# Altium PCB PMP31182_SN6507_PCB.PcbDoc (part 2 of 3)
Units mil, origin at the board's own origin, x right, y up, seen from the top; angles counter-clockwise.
Board outline 4922 x 2266 mil, 4 copper layers (Top Layer, Signal Layer 1, Signal Layer 2, Bottom Layer), stack 77.9 mil thick; 174 components, 102 nets, 540 pads, 580 vias.
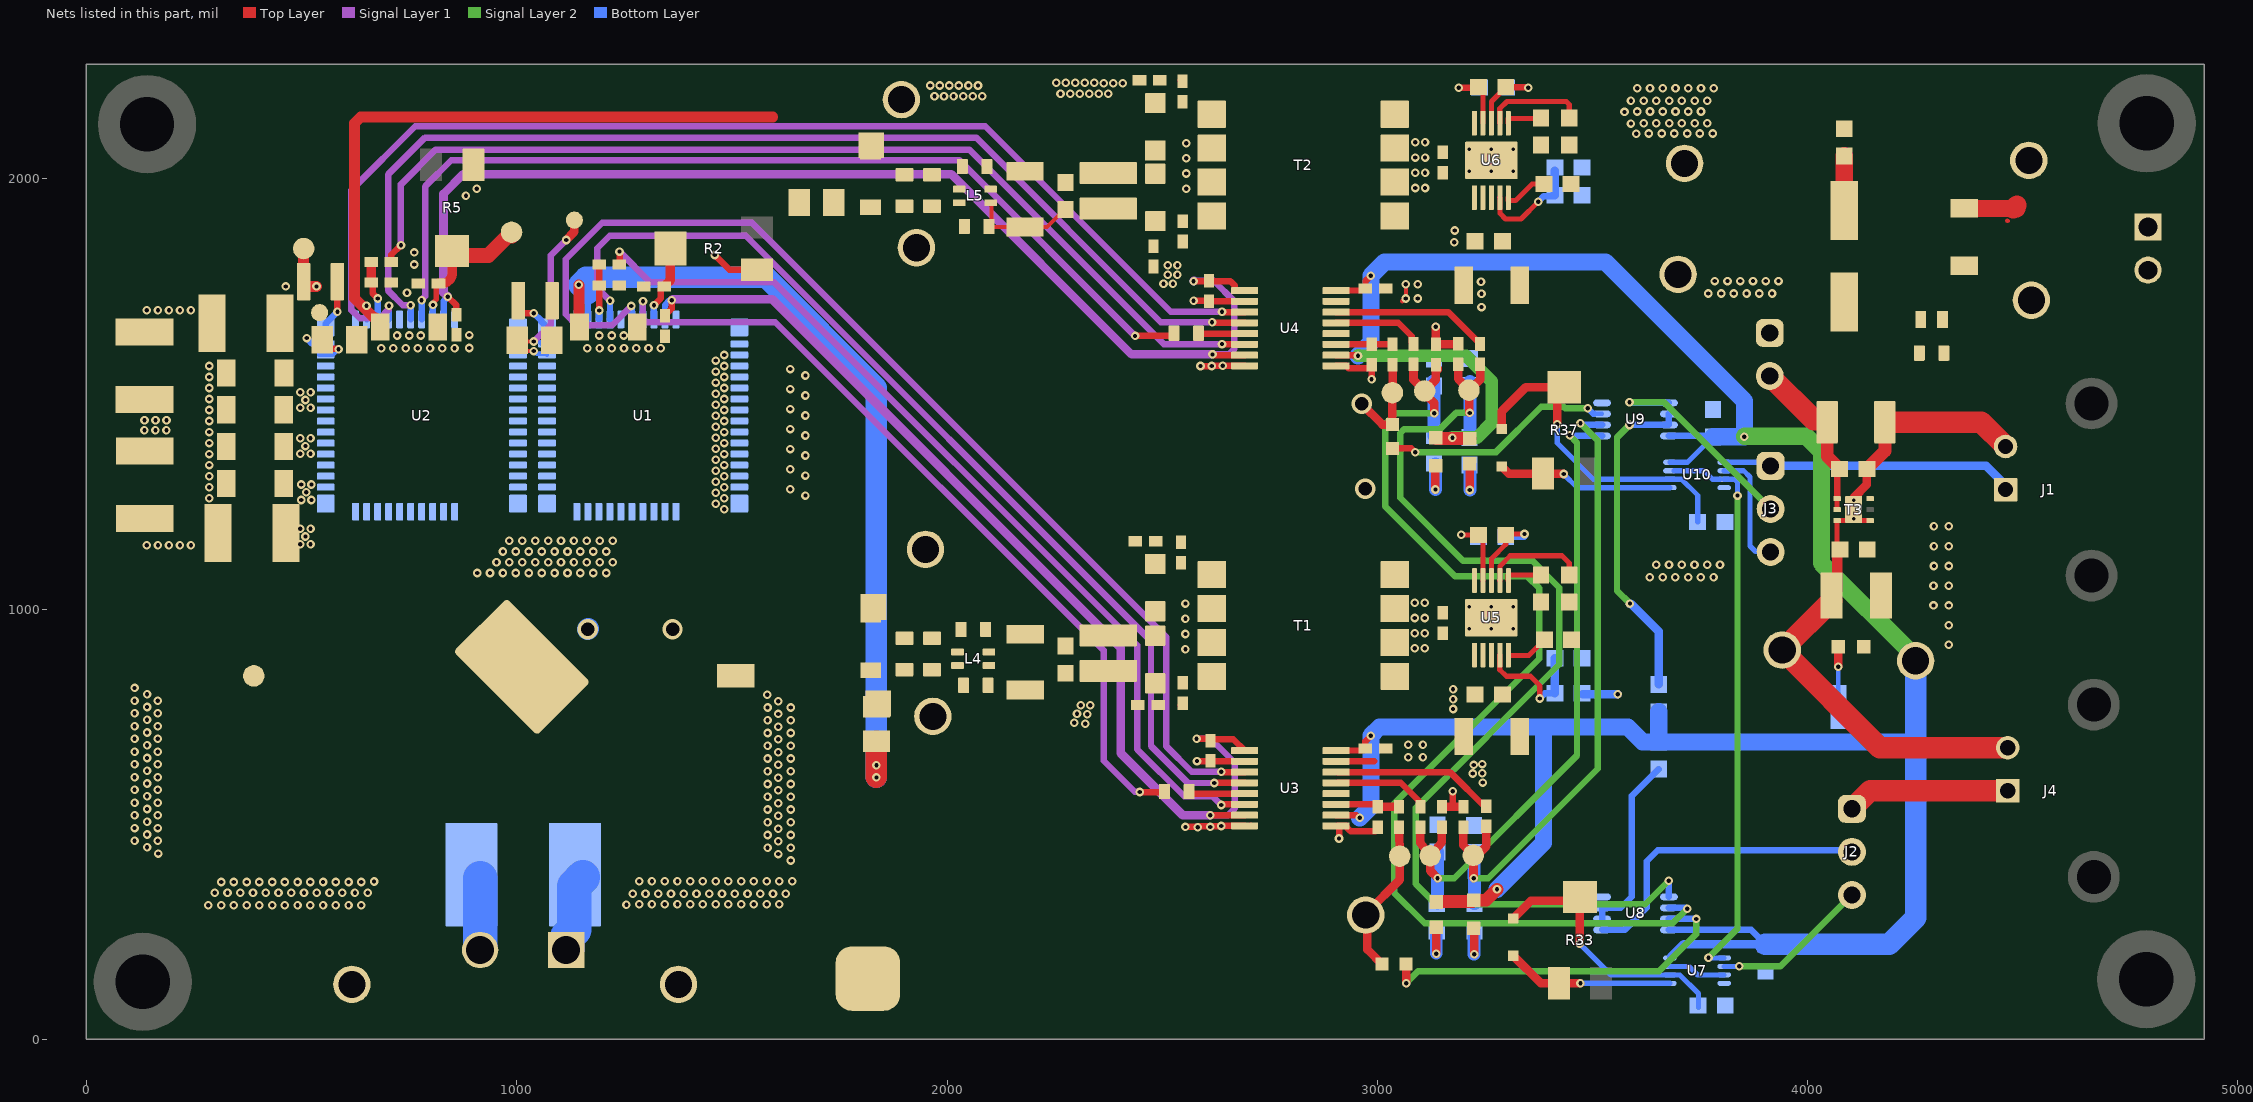
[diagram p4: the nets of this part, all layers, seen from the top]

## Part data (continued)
R2 R5: library part CMP-0002064-2, "Trimmer, 200 K, 0.25 W, SMD", Manufacturer=Bourns, Supplier Part Number 1=3224X-1-204ECT-ND
R4 R9 R18 R24 R27 R31 R41: library part CMP-0089143-1, "0 Ohms Jumper 0.1W, 1/10W Chip Resistor 0603 (1608 Metric) Automotive AEC-Q200 Thick Film", Digikey Part Number=P0.0GCT-ND, Manufacturer=Panasonic, Mouser Part Number=667-ERJ-3GEY0R00V, Operating Temperature Range="-55°C to +155°C", Power_W=100mW, TempCo=-100/+600ppm/°C, Tolerance_%=5%
R6 R15 R19 R20 R39 R40: library part CMP-0026902-3, "RES, 300, 5%, 0.063 W, AEC-Q200 Grade 0, 0402", Manufacturer=Vishay-Dale, Power_W=63mW, Supplier Part Number 1=541-300JCT-ND, TempCo="200 ppm/C", Tolerance_%=5%, Value2=0.063W, Value_Code=300R, ValueDisplayed=300
R7 R16: library part CMP-0026404-2, "RES, 49.9, 1%, 0.063 W, AEC-Q200 Grade 0, 0402", Manufacturer=Vishay-Dale, Power_W=63mW, Supplier Part Number 1=541-49.9LCT-ND, TempCo="100 ppm/C", Tolerance_%=1%, Value2=0.063W, Value_Code=49R9, ValueDisplayed=49.9
R8 R26: library part CMP-0024440-2, "RES, 6.81 k, 0.1%, 0.1 W, 0603", Manufacturer="Yageo America", Power_W=100mW, TempCo="25 ppm/C", Tolerance_%=0.1%, Value2=0.1W, Value_Code=6k81, ValueDisplayed=6.81k
R10 R12 R14 R17 R21: library part CMP-0025797-4, "RES, 3.3 k, 5%, 0.1 W, AEC-Q200 Grade 0, 0603", Manufacturer=Vishay-Dale, Power_W=100mW, Supplier Part Number 1=541-3.3KGCT-ND, TempCo="200 ppm/C", Tolerance_%=5%, Value2=0.1W, Value_Code=3k30, ValueDisplayed=3.3k
R11: library part CMP-0022714-3, "RES, 0.33, 1%, 0.1 W, AEC-Q200 Grade 0, 0603", Manufacturer=Panasonic, Power_W=100mW, Supplier Part Number 1=P.33AJCT-ND, TempCo="300 ppm/C", Tolerance_%=1%, Value2=0.1W, Value_Code=R330, ValueDisplayed=0.33
R13 R28: library part CMP-0023919-2, "RES, 1.00 k, 0.1%, 0.1 W, 0603", Manufacturer="Yageo America", Power_W=100mW, Supplier Part Number 1=603-RT0603BRD071KL, TempCo="25 ppm/C", Tolerance_%=0.1%, Value2=0.1W, Value_Code=1k00, ValueDisplayed=1.00k
R23 R30: library part CMP-0024307-2, "RES, 50.5 k, 0.1%, 0.1 W, 0603", Manufacturer="Yageo America", Power_W=100mW, TempCo="25 ppm/C", Tolerance_%=0.1%, Value2=0.1W, Value_Code=50k5, ValueDisplayed=50.5k
R25 R32: library part CMP-0023919-2, "R", Manufacturer="Yageo America", PartNumber=RT0603BRD071KL, Power_W=100mW, Supplier Part Number 1=603-RT0603BRD071KL, TempCo="25 ppm/C", Tolerance_%=0.1%, Value2=0.1W, Value_Code=1k00, ValueDisplayed="TBD a/c to Slew Rate"
R29 R42: library part CMP-0022914-5, "RES, 21.0 k, 1%, 0.1 W, 0603", Manufacturer=Yageo, Power_W=100mW, Supplier Part Number 1=311-21.0KHRCT-ND, TempCo="100 ppm/C", Tolerance_%=1%, Value2=0.1W, Value_Code=21k0, ValueDisplayed=21.0k
R33 R37: library part CMP-0002062-2, "Trimmer, 5 K, 0.25 W, SMD", Manufacturer=Bourns, Supplier Part Number 1=3224X-1-502ECT-ND
R34 R38: library part CMP-0025697-4, "RES, 0, 5%, 0.1 W, AEC-Q200 Grade 0, 0603", Manufacturer=Vishay-Dale, Power_W=100mW, Supplier Part Number 1=541-0.0GCT-ND, TempCo="200 ppm/C", Tolerance_%=5%, Value2=0.1W, Value_Code=0000, ValueDisplayed=0
R35 R36: library part CMP-0082530-1, "RES, 100 k, 5%, 0.1 W, 0603", Manufacturer=Vishay-Dale, Power_W=100mW, Supplier Part Number 1=541-3992-1-ND, TempCo="200 ppm/C", Tolerance_%=5%, Value2=0.1W, Value_Code=100k
R43 R45: library part CMP-0023640-2, "RES, 106 k, 0.1%, 0.1 W, 0603", Manufacturer="Yageo America", Power_W=100mW, TempCo="25 ppm/C", Tolerance_%=0.1%, Value2=0.1W, Value_Code=106k
R46 R47 R48 R49: library part CMP-0026763-1, "RES, 100, 1%, 0.063 W, AEC-Q200 Grade 0, 0402", Manufacturer="Stackpole Electronics Inc", Power_W=63mW, Supplier Part Number 1=RMCF0402JT100RCT-ND, TempCo="100 ppm/C", Tolerance_%=1%, Value2=0.063W, Value_Code=100R, ValueDisplayed=100
SH-J1 SH-J2 SH-J3: library part CMP-0003623-3, "Shunt, 100mil, Gold plated, Black", Alternate Manufacturer=3M, Alternate PartNumber=969102-0000-DA, Manufacturer=Samtec, Supplier Part Number 1=SAM8858-ND
T1 T2: library part CMP-0095871-1, "Push-Pull Transformers for Texas Instruments SN6507 Push Pull Driver", Frequency_Fixed=1MHz, Manufacturer=Coilcraft, Operating Temperature Range=to, Part Number=TX1-ZB1459-BED, Voltage_Isolation_Vrms=2500Vrms
T3: library part CMP-0086086-2, "150-mA High-Voltage Ultralow-IQ Low-Dropout Regulator, DRV0006A (WSON-6)", Alternate Manufacturer="Texas Instruments"
Top_FET_PWM: library part CMP-0055144-1, "Test Point, Compact, White, TH", Color=White, Manufacturer=Keystone, Supplier Part Number 1=36-5007-ND
TP1: library part CMP-0055153-1, "Test Point, Compact, SMT", Manufacturer=Keystone, Supplier Part Number 1=36-5016TR-ND
TP2: library part CMP-0003968-1, "Test Point, SMT", Manufacturer=Harwin, Supplier Part Number 1=952-2664-1-ND
U1 U2: library part CMP-0089968-1, "650-V 30-mΩ GaN FET with Integrated Driver and Protection", Manufacturer="Texas Instruments", Max Supply Voltage=18V, Min Supply Voltage=7.5V, Nominal Supply Current=540uA, Operating Temperature Range="-40°C to +125°C", Output Voltage=520V
U3 U4: library part CMP-0090469-1, "General Purpose Digital Isolator 2500Vrms 4 Channel 100Mbps 85kV/µs CMTI 16-SSOP (0.154\", 3.90mm Width)", Digikey Part Number=296-51207-1-ND, Manufacturer="Texas Instruments", Max Supply Voltage=5.5V, Min Supply Voltage=2.25V, Mouser Part Number=595-ISO7741FQDBQRQ1, Nominal Supply Current=1.5-18mA, Operating Temperature Range="-40°C to +125°C"
U5 U6: library part CMP-0095407-1, "Low-Emission 36V Push-Pull Transformer Driver with Duty Cycle Control for Isolated Power Supplies", Manufacturer="Texas Instruments", Operating Temperature Range="-55°C to +150°C"
U7 U10: library part CMP-0051969-2, "Triple Schmitt-Trigger Inverter, DCU0008A (VSSOP-8)", F @ Nom Voltage(Max)(Mhz)=150, Generic Part Number=SN74LVC3G14, ICC @ Nom Voltage(Max)(mA)=0.01, Manufacturer="Texas Instruments", Operating Temperature Range="-40 to 125 C", Rating=Catalog, tpd @ Nom Voltage(Max)(ns)=9.2,5.7,5.4,4.3, Voltage(Nom)(V)=1.8,2.5,3.3,5
U8 U9: library part CMP-0051803-1, "Automotive Catalog Dual 2-Input Positive-AND Gate, DCT0008A, LARGE T&R", F @ Nom Voltage(Max)(Mhz)=150, Generic Part Number=SN74LVC2G08-Q1, ICC @ Nom Voltage(Max)(mA)=0.01, Manufacturer="Texas Instruments", Operating Temperature Range(C)="-40 to 85", Rating=Automotive, tpd @ Nom Voltage(Max)(ns)=9,5.1,4.7,3.8, Voltage(Nom)(V)=1.8,2.5,3.3,5

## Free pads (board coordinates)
  round 50 smd paste-30: 1(389,845) 1(505,1838) 1(988,1876) 1(3035,1503) 1(3052,426) 1(3110,1507) 1(3123,427) 1(3213,1509) 1(3223,428)
  round 40 smd paste-30: 1(542,1689) 1(1134,1904)
  round 228.35 hole 125.98: 2(131,134) 2(141,2127) 2(4787,140) 2(4788,2129)
  rect 60x60 smd: 3(1824,2078) 3(1829,1005) 3(1840,781)
  rrect50% 150x150 smd: Load_GND(1816.25,141.5)

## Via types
v1: diameter 20, hole 10, Top Layer to Bottom Layer, tented both sides, 562 vias
v2: diameter 19.68, hole 7.87, Top Layer to Bottom Layer, 14 vias
v3: diameter 47.24, hole 31.5, Top Layer to Bottom Layer, 4 vias

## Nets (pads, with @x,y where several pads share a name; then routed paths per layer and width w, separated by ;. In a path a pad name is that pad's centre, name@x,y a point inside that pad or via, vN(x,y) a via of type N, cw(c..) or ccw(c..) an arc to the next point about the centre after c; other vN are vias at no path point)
5V: C9.1 C26.1 C41.2 C44.2 C48.1 C53.1 HS_FLT.1 HS_OC.1 LDO5V.1 LDO.1 LS_FLT.1 LS_OC.1 R35.1 R36.2 T3.6 U3.10 U3.16 U4.10 U4.16 U7.8 U8.8 U9.8 U10.8 | length 6856
  Top Layer w15: U3.10@2904.08,521.5 2951.15,521.5 ; U3.16@2904.08,671.5 2967.88,671.5 C26.1@2972.38,676 2972.38,693.38 v1(2985,706) ; U4.16@2904.33,1740.75 U4.16@2904.08,1740.5 2962.26,1740.5 C9.1@2969.57,1747.81 ; U4.10@2905.08,1590.5 2905.65,1589.93 2954.07,1589.93 v1(2955,1589) ; C9.1@2972.57,1744.81 2972.57,1762.57 v1(2985,1775)
  Top Layer w30: HS_FLT.1@3137,319.53 3137.75,320.28 3220.8,320.28 HS_OC.1@3224,323.48 3252.48,323.48 v1(3278,349) ; LS_OC.1@3137.95,1396.53 v1@3172.57,1396.53 ; v1@3176.48,1396.53 LS_FLT.1@3215,1396.53
  Signal Layer 2 w30: v1@2956,1590 v1(2955,1589) 3206,1589 3266,1529 3266,1433 3231.48,1398.48 v1(3174.52,1398.48)
  Signal Layer 2 w40: v1(3853,1401) 3854,1402 3997,1402 4032,1367 4032,1107 4251,888 LDO5V.1@4251,880
  Bottom Layer w10: 4045.91,221.5 4045.91,221.65
  Bottom Layer w12: U10.8@3680.02,1341.37 3720.87,1341.37 C44.2@3780,1400.5
  Bottom Layer w15: U8.8@3677.76,254.61 3868.88,254.61 C41.2@3902,221.5 ; U9.8@3677.76,1402.61 C44.2@3777.89,1402.61
  Bottom Layer w20: R35.1@3654,693.5 3660.7,693.5 R35.1@3662.7,691.5 ; U7.8@3683.74,193.26 3711.98,221.5 C41.2@3902,221.5 ; 4245.5,691.5 4251,697
  Bottom Layer w40: v1(2955,1589) 2985,1619 v1(2985,1775) 3017,1807 3530,1807 3853,1484 v1(3853,1401) ; v1(2959,515) 2985,541 v1@2985,701.41 ; v1(2985,706) 3005,726 3386,726 ; v1(3278,349) 3386,457 3386,726 ; R35.1@3654,691.5 3616.5,691.5 3582,726 3386,726 ; R35.1@3654,693.5 R36.2@3654,761.5 ; R35.1@3662.7,691.5 4245.5,691.5 ; C44.2@3780,1400.5 v1@3852.5,1400.5
  Bottom Layer w50: C41.2@3902,221.5 4045.91,221.5 4189.5,221.5 4251,283 4251,697 LDO5V.1@4251,880
  other v1: 4328,917.08 4328,962.91 4292.48,1008.75 4328,1008.75 4292.48,1054.58 4328,1054.58 4293.48,1100.41 4328,1100.41 4293.48,1146.46 4328,1146.46 4293.48,1192.46 4328,1192.46
5V_H: C2.1 C10.1 U1.51 U3.1 U3.7 | length 2474.7
  Top Layer w10: C10.1@2610.62,699 C10.1@2612,697.62
  Top Layer w15: C2.1@1344.59,1681.62 1344.59,1685.56 1348.9,1689.87 1351.67,1689.87 1360.45,1698.66 v1(1360.45,1718.06) ; v1(2580,699) C10.1@2610.62,699 ; C10.1@2612,697.62 2665.36,697.62 U3.1@2691.48,671.5 ; v1@2612.5,521.5 U3.7@2691.48,521.5
  Signal Layer 1 w15: v1(2580,699) 2613.08,699 2669,643.08 2669,537 2653,521 v1(2612,521)
  Signal Layer 1 w20: v1(1360.45,1718.06) 1362.37,1719.97 1369.44,1719.97 1594,1720 2404,910 2404,665 2548,521 v1(2612,521)
  Bottom Layer w15: U1.51@1344.59,1673.4 1344.59,1706.59 1355.1,1717.1 1359.5,1717.1 v1(1360.45,1718.06)
5V_L: C12.1 C27.1 U2.51 U4.1 U4.7 | length 2820.4
  Top Layer w15: v1(840,1726) 860,1706 C12.1@860,1684.62 ; v1(2573,1762) 2607.76,1762 C27.1@2609,1763.24 2612.07,1763.24 2613.31,1762 2658.7,1762 2669.13,1751.57 2669.13,1741.07 2669.7,1740.5 U4.1@2691.48,1740.5 ; v1(2617,1592) 2618.35,1592 2619.85,1590.5 U4.7@2691.48,1590.5
  Signal Layer 1 w15: v1@2574,1763 2620,1763 2668,1715 2668,1605.01 2654.99,1592 v1(2617,1592)
  Signal Layer 1 w20: v1(840,1726) 830,1736 830,1965 876,2011 2010,2011 2429,1592 v1(2617,1592) ; v1(2573,1762) v1@2574,1763
  Bottom Layer w15: U2.51@830.17,1673.4 830.17,1716.17 v1(840,1726)
15V: 15VIN.1 C7.1 J6.2 L3.1 R4.1
15V_F: 15VINF.1 C4.1 C8.1 C22.1 C31.1 C32.1 C62.1 C63.1 J7.1 L3.2 R4.2 R8.2 R26.2 T1.2 T1.3 T2.2 T2.3 U5.3 U6.3 | length 84.6
  Bottom Layer w10: R8.2@3475.5,804.55 R8.2@3478.05,802
  Bottom Layer w20: R8.2@3478.05,802 v1(3559,802)
  other v1: 3087,908.83 3110,908.83 3087,944.16 3110,944.16 3087,979.5 3110,979.5 3087,1014.83 3110,1014.83 3633.38,1074 3663,1074 3692.62,1074 3722.23,1074 3751.85,1074 3781.46,1074 3648.19,1103 3677.81,1103 3707.42,1103 3737.04,1103 3766.65,1103 3796.27,1103 3769.31,1733.5 3798.92,1733.5 3828.54,1733.5 3858.15,1733.5 3887.77,1733.5 3917.38,1733.5 3784.12,1762.5 3813.73,1762.5 3843.35,1762.5 3872.96,1762.5 3902.58,1762.5 3932.19,1762.5 3088,1978.83 3111,1978.83 3088,2014.16 3111,2014.16 3088,2049.5 3111,2049.5 3088,2084.83 3111,2084.83
Bot_FET_FAULT: C52.1 C57.1 pad.1@3213,1509 R14.1 R40.2 U8.5 | length 2599.2
  Top Layer w20: C57.1@3188,1569.38 3188,1535.24 3204.07,1517.24 pad.1@3206.97,1514.34 ; pad.1@3213,1509 3214,1508 3214,1457 v1(3215,1456) ; pad.1@3215,1510.85 3239,1533 R40.2@3239,1569
  Signal Layer 2 w15: v1(3215,1456) 3183,1456 3145.49,1418.49 3062.49,1418.49 3053,1409 3053,1259 3200,1112 3361,1112 3423,1050 3423,872 3089,538 3089,361.5 3136.5,314 3622.38,314 v1@3677.19,368.81
  Bottom Layer w10: v1(3677,369) v1@3677.38,368.62 ; U8.5@3677.38,331.76 U8.5@3677.76,331.39
  Bottom Layer w15: U8.5@3677.38,331.76 v1@3677.38,368.62
  Bottom Layer w30: R14.1@3215,1398.5 v1(3215,1456) C52.1@3215,1529.5
Bot_FET_OC: C55.1 C56.1 pad.1@3110,1507 R17.1 R39.2 U8.6 | length 2712.8
  Top Layer w20: R39.2@3084,1569 3084,1533 pad.1@3110,1507 ; v1(3132,1455) 3132,1479.73 3110,1501.73 pad.1@3110,1507 ; C56.1@3140.7,1557.02 C56.1@3136,1568.38 3136,1533 pad.1@3110,1507
  Signal Layer 2 w15: v1(3132,1455) 3044,1455 3018,1429 3018,1239 3181,1076 3349,1076 3376,1049 3376,885 3039,548 3039,341 3110,270 3686,270 v1(3720,304)
  Bottom Layer w12: v1@3716.04,305.8 3717.84,304 v1(3720,304)
  Bottom Layer w15: U8.6@3677.76,305.8 v1@3716.04,305.8
  Bottom Layer w30: C55.1@3131,1530.5 3132,1529.5 v1(3132,1455) R17.1@3132,1403
Bot_FET_PWM: pad.1@3035,1503 R16.1 R38.2 | length 230.1
  Top Layer w20: v3(2964,1477) 3012,1429 R38.2@3035,1429 pad.1@3035,1503 3035.5,1537.5 R16.1@3035.5,1568.26
Bot_FET_TEMP: U4.12
FAULT_H: U1.46 U3.4 | length 2361.7
  Top Layer w10: U3.4@2705.23,595.25 U3.4@2706.48,596.5
  Top Layer w15: v1@2621.5,596.5 U3.4@2691.48,596.5
  Signal Layer 1 w15: v1(1217,1717) 1187,1747 1187,1839 1216,1868 1532,1868 2474,926 2474,682 2560,596 v1(2621,596)
  Bottom Layer w15: U1.46@1216.64,1673.4 1216.82,1673.58 1216.82,1712.82 v1@1217,1713
FAULT_L: U2.46 U4.3 | length 2737.7
  Top Layer w15: v1@2639.5,1690.5 U4.3@2691.48,1690.5
  Signal Layer 1 w15: v1(703.13,1705.13) 702.18,1704.18 702.18,1696.18 682,1676 635,1676 616,1695 616,1974 764,2122 2089,2122 2520,1691 v1(2639,1691)
  Bottom Layer w15: U2.46@702.21,1673.4 702.59,1673.78 702.59,1704.59 v1(703.13,1705.13)
GND_HV: C11.1 C12.2 C13.1 C15.2 C16.2 C17.2 C18.2 C19.2 C20.2 C21.2 C23.1 C27.2 C33.2 C34.2 C38.2 C43.1 C49.2 D5.2 GNDHV.1 ISO15VGND.1 J5.1 L2.1 L5.1 pad.1@505,1838 pad.3@1824,2078 pad.Load_GND R5.1 R31.2 R48.1 R49.1 T2.6 T2.7 TP2.1 U2.17 U2.18 U2.19 U2.20 U2.21 U2.22 U2.23 U2.24 U2.25 U2.26 U2.27 U2.28 U2.29 U2.30 U2.31 U2.32 U2.33 U2.34 U2.35 U2.36 U2.37 U2.38 U2.39 U4.2 U4.8 | length 598.3
  Top Layer w10: C20.2@453,1138.74 C20.2@453,1159 ; pad.1@504.63,1834.63 pad.1@505,1835
  Top Layer w15: v1(2573,1717) 2602.19,1717 2602.5,1716.69 2602.5,1715.5 U4.2@2691.48,1715.5 ; v1(2589,1565) v1(2615,1565) 2615.5,1565.5 2640.5,1565.5 v1(2641,1566) ; v1@2641.5,1565.5 U4.8@2691.48,1565.5
  Top Layer w25: pad.1@505,1835 504.63,1824.63 504.63,1750 v1(534.63,1750)
  Bottom Layer w10: C49.2@1109.47,344 C49.2@1148.47,383
  Bottom Layer w80: J5.1@1115,208 1117.32,210.32 1117.32,238.4 1133.57,254.64 1133.57,356.57 C49.2@1154,377
  other v1: 1255,313 1284.62,314 1314.23,314 1343.85,314 1373.46,314 1403.08,314 1432.69,314 1462.31,314 1491.92,314 1521.54,314 1551.15,314 1580.77,314 1610.38,314 1269.81,339 1299.42,339 1329.04,339 1358.65,339 1388.27,339 1417.88,339 1447.5,339 1477.11,339 1506.73,339 1536.34,339 1565.96,339 1595.57,339 1625.19,339 1284.62,368 1314.23,368 1343.85,368 1373.46,368 1403.08,368 1432.69,368 1462.31,368 1491.92,368 1521.54,368 1551.15,368 1580.77,368 1610.38,368 1640,368 1637,416 1608,430.81 1583,445.62 1637,445.62 1608,460.43 1583,475.23 1637,475.23 1608,490.04 1583,504.85 1637,504.85 1608,519.66 1583,534.46 1637,534.46 1608,549.27 1583,564.08 1637,564.08 1608,578.89 1583,593.69 1637,593.69 1608,608.5 1583,623.31 1637,623.31 1608,638.12 1583,652.92 1637,652.92 1608,667.73 1583,682.54 1637,682.54 1608,697.35 1583,712.15 1637,712.15 1608,726.96 1583,741.77 1637,741.77 1608,756.58 1583,771.38 1637,771.38 1608,786.19 1582,801 497,1150.87 521,1150.87 509,1168.87 497,1186.87 521,1186.87 499,1253.64 523,1253.64 511,1271.64 499,1289.64 523,1289.64 497,1361 521,1361 509,1379 497,1397 521,1397 134.82,1416 160.41,1416 186,1416 135,1439 160.59,1439 186.18,1439 497,1468 521,1468 509,1486 497,1504 521,1504 685,1606 713.43,1606 741.86,1606 770.29,1606 798.71,1606 827.14,1606 855.57,1606 890,1607 722,1636 750,1636 777,1636 890,1637 745,1735 463,1750 2503,1756 2525,1756 2513,1777 2535.5,1777 2513,1799.5 2535.5,1799.5 762,1801 762,1829 882,1961 907,1977 2556,1977 2556,2012.33 2556,2047.67 2556,2083 1970.84,2191.79 1993.04,2191.79 2015.24,2191.79 2037.44,2191.79 2059.64,2191.79 2081.84,2191.79 2263.84,2197.79 2286.04,2197.79 2308.24,2197.79 2330.44,2197.79 2352.64,2197.79 2374.84,2197.79 1961,2217 1983.2,2217 2005.4,2217 2027.6,2217 2049.8,2217 2072,2217 2364.36,2222 2386.43,2222 2408.5,2222 2254,2223 2276.07,2223 2298.14,2223 2320.21,2223 2342.29,2223
  other v3: 1362.2,953
GND_LV: C6.2 C7.2 C8.2 C9.2 C14.1 C22.2 C26.2 C30.2 C31.2 C32.2 C37.2 C39.2 C40.2 C41.1 C44.1 C45.2 C46.2 C47.2 C48.2 C50.2 C51.2 C52.2 C53.2 C54.1 C55.2 C56.2 C57.2 C62.2 C63.2 GND_LV.1 GNDLV.1 GNDLVF.1 J1.2 J4.2 J6.1 R11.1 R13.1 R21.1 R23.1 R25.1 R28.1 R29.1 R30.1 R32.1 R42.1 R43.1 R45.1 T3.3 T3.4 T3.7@4107,1231.35 U3.9 U3.15 U4.9 U4.15 U5.2 U5.9 U5.11 U6.2 U6.9 U6.11 U7.4 U8.4 U9.4 U10.4 | length 2629.9
  Top Layer w10: U3.9@2904.08,496.5 2907.93,496.5 U3.9@2911,493.43 ; C14.1@2986,1568.26 C14.1@2986.63,1567.63 ; C6.2@3001,489.56 C6.2@3001,493.5 ; 3057.8,1715.5 3064.29,1722 v1(3066,1722) 3067,1722 3066.5,1722.5 3066.5,1754.5 v1(3066,1755) ; 3175,543.97 3178.35,540.62 ; C30.2@3235.2,1172.7 C30.2@3235.5,1172.4 C30.2@3245.32,1162.59 ; C37.2@3236.5,2212 3237.5,2213 C37.2@3245.32,2205.19 ; C48.2@4051.91,1035.63 C48.2@4055.91,1031.63 C48.2@4055.91,1019.91 ; C53.2@4068.61,1145.52 C53.2@4075.5,1138.63 ; T3.7@4103.06,1205.76 v2(4107,1209.69) T3.7@4110.94,1205.76 ; v2(4107,1253) T3.7@4113.95,1253 ; C7.2@4356,1931.93 C7.2@4377.62,1931.67 ; 4464.07,1902.93 4465,1902
  Top Layer w12: v1(3195,1172.7) C30.2@3235.2,1172.7 ; U5.9@3245.32,1066.61 C30.2@3245.32,1162.59 ; U6.9@3245.32,2129.61 C37.2@3245.32,2198.19 ; C53.2@4068.61,1145.52 T3.3@4068.61,1205.76 T3.7@4103.06,1205.76 ; T3.7@4110.94,1205.76 T3.4@4145.39,1205.76
  Top Layer w15: U3.15@2904.08,646.5 2993,646.5 ; U4.9@2904.08,1565.5 2927.5,1565.5 2933,1560.01 2981.69,1560.01 2986,1564.32 C14.1@2986,1568.26 ; U3.9@2907.93,496.5 2927.5,496.5 2928.08,495.93 2928.08,493.79 2937.86,484 2995.44,484 C6.2@3001,489.56 ; v1(2911,467) U3.9@2911,493.43 ; v1(2986.63,1534) C14.1@2986.63,1567.63 ; 3175,543.97 v1(3175,577) ; v1(3189,2212) C37.2@3236.5,2212
  Top Layer w20: v1(3136,1656) C56.2@3136,1615.62 3187,1615.62 C57.2@3188,1616.62 ; C40.2@3150,540.62 3178.35,540.62 C39.2@3200,540.62 ; U6.11@3260,2038 U6.11@3265,2043 ; T3.7@4107,1231.35 v2(4107,1253) 4107,1259.01 4137.5,1289.5 C47.2@4137.5,1325.63
  Top Layer w25: C48.2@4055.91,1031.63 4069,1044.72 4069,1132.43 4075.2,1138.63 C53.2@4075.5,1138.63
  Top Layer w30: C47.2@4137.5,1325.63 4179.35,1367.49 C54.1@4179.35,1434.63
  Top Layer w40: C7.2@4364,1931.93 4485.98,1930.48
  Top Layer w45: 4477.98,1930.48 4486.42,1938.72
  Top Layer w50: C48.2@4055.91,1019.91 GND_LV.1@3941,905 4168,678 J4.2@4465,678 ; C54.1@4179.35,1434.63 4403.37,1434.63 J1.2@4460,1378
  other v1: 3245,597 3222,618 3244,619 3224,638 3244,640 3072,656 3106,656 3072,685 3106,685 3176,768 3176,791 3176,814 3242,1702 3094,1722 3242,1733 3094,1755 3241,1761 3179,1853 3180,1880 3601.5,2104.5 3631.12,2105.5 3660.73,2105.5 3690.35,2105.5 3719.96,2105.5 3749.58,2105.5 3779.19,2105.5 3589.31,2128.5 3618.92,2129.5 3648.54,2129.5 3678.15,2129.5 3707.77,2129.5 3737.38,2129.5 3767,2129.5 3574.5,2155.5 3604.12,2156.5 3633.73,2156.5 3663.35,2156.5 3692.96,2156.5 3722.58,2156.5 3752.19,2156.5 3589.31,2181.5 3618.92,2181.5 3648.54,2181.5 3678.15,2181.5 3707.77,2181.5 3737.38,2181.5 3767,2181.5 3604.12,2210.5 3633.73,2210.5 3663.35,2210.5 3692.96,2210.5 3722.58,2210.5 3752.19,2210.5 3781.81,2210.5
  other v2: 3213.82,954.41 3265,954.41 3316.18,954.41 3213.82,1005.59 3265,1005.59 3316.18,1005.59 3213.82,2017.41 3265,2017.41 3316.18,2017.41 3213.82,2068.59 3265,2068.59 3316.18,2068.59
  other v3: 2972,1280
HVBUS: C15.1 C16.1 C17.1 C18.1 C19.1 C20.1 C21.1 C38.1 C49.1 HVIN.1 J5.2 pad.1@389,845 U1.1 U1.2 U1.3 U1.4 U1.5 U1.6 U1.7 U1.8 U1.9 U1.10 U1.11 U1.12 U1.13 U1.14 U1.15 U1.16 | length 169.8
  Bottom Layer w10: C49.1@907.53,383 C49.1@909.47,381.06
  Bottom Layer w80: J5.2@915,208 C49.1@915,375.06
  other v1: 283.5,312 313.12,312 342.73,312 372.35,312 401.96,312 431.58,312 461.19,312 490.81,312 520.42,312 550.04,312 579.65,312 609.27,312 638.88,312 298.31,341 327.92,341 357.54,341 387.15,341 416.77,341 446.38,341 476,341 505.62,341 535.23,341 564.85,341 594.46,341 624.08,341 653.69,341 313.12,366 342.73,366 372.35,366 401.96,366 431.58,366 461.19,366 490.81,366 520.42,366 550.04,366 579.65,366 609.27,366 638.88,366 668.5,367 167,432 141,446.81 112,461.62 166,461.62 141,476.42 112,491.23 166,491.23 141,506.04 112,520.85 166,520.85 141,535.65 112,550.46 166,550.46 141,565.27 112,580.08 166,580.08 141,594.88 112,609.69 166,609.69 141,624.5 112,639.31 166,639.31 141,654.11 112,668.92 166,668.92 141,683.73 112,698.54 166,698.54 141,713.34 112,728.15 166,728.15 141,742.96 112,757.77 166,757.77 141,772.57 112,787.38 166,787.38 141,802.19 112,817 140.59,1148.52 166.18,1148.52 191.77,1148.52 217.36,1148.52 242.95,1148.52 1482.43,1232.46 1462.43,1245.05 285.22,1258.05 1482.43,1258.05 1462.43,1270.64 285.22,1283.64 1482.43,1283.64 1462.43,1296.23 285.22,1309.23 1482.43,1309.23 1462.43,1321.82 285.22,1334.82 1482.43,1334.82 1462.43,1347.41 285.22,1360.41 1482.43,1360.41 1462.43,1373 285.22,1386 1482.43,1386 1462.43,1398.59 285.22,1411.59 1482.43,1411.59 1462.43,1424.18 285.22,1437.18 1482.43,1437.18 1462.43,1449.77 285.22,1462.77 1482.43,1462.77 1462.43,1475.36 285.22,1488.36 1482.43,1488.36 1462.43,1500.95 285.22,1513.95 1482.43,1513.95 1462.43,1526.54 285.22,1539.54 1482.43,1539.54 1462.43,1552.13 285.22,1565.13 1482.43,1565.13 1462.43,1577.73 1482.43,1590.73 140.59,1694.48 166.18,1694.48 191.77,1694.48 217.36,1694.48 242.95,1694.48
IN_H: C5.2 R6.2 U1.45 | length 116
  Top Layer w15: C5.2@1190.39,1749.38 1192,1747.77 v1(1192,1694) ; C5.2@1191.38,1752 R6.2@1191.38,1791
  Bottom Layer w15: U1.45@1191.05,1673.4 1191.42,1673.78 1191.42,1693.42 v1(1192,1694)
IN_L: C23.2 R15.2 U2.45 | length 139.7
  Top Layer w15: C23.2@661.47,1758.91 665.41,1754.97 665.41,1733.59 v1(677,1722)
  Top Layer w22: C23.2@661.47,1758.91 R15.2@661.47,1807
  Bottom Layer w15: U2.45@676.62,1673.4 v1@676.62,1721.62
ISO_15V_H: C24.1 C25.1 D2.1 ISO15VH.1 L4.2 pad.3@1840,781 R1.1 R9.2
ISO_15V_H_B: C28.1 C29.1 L4.3 L6.2 R9.1
ISO_15V_L: C33.1 C34.1 D5.1 ISO15VL.1 L5.2 R3.1 R27.2
ISO_15V_L_B: C35.1 C36.1 L5.3 L7.2 R27.1 | length 256.2
  Top Layer w10: L5.3@2103.42,1944.69 2103.42,1892.51 2098.94,1888.04 2103.42,1888.04 C36.1@2181,1888.04 2232.54,1888.04 2273,1928.5 C35.1@2277.84,1923.66
ISO_RET_H_B: C28.2 C29.2 L4.4 R24.1
ISO_RET_L_B: C35.2 C36.2 L5.4 R31.1
NC_PGND1: U2.43
NC_PGND2: U2.47
NC_PGND3: U2.52
NC_SW1: U1.43
NC_SW2: U1.47
NC_SW3: U1.52
NetC1_1: C1.1 R1.2 U1.44 | length 1983
  Top Layer w25: v1(1144,1754) 1145.07,1752.93 C1.1@1145.07,1656
  Top Layer w50: v1(1836,609) R1.2@1836,693
  Bottom Layer w15: U1.44@1165.46,1673.4 1165.46,1732.54
  Bottom Layer w50: 1165.46,1732.54 v1(1144,1754) 1161,1771 1580,1771 1836,1515 v1(1836,609)
  other v1: 1836,637
NetC4_2: C4.2 R11.2 | length 127.2
  Top Layer w40: C4.2@4085,1926.3 R11.2@4085,2053.5
NetC6_1: C6.1 R7.2 U3.11 | length 149.7
  Top Layer w15: U3.11@2904.08,546.5 2996.69,546.5 3001,542.19 C6.1@3001,540.75
  Top Layer w20: C6.1@3001,540.75 R7.2@3050.5,540.75
NetC11_2: C11.2 R3.2 U2.44 | length 1509.8
  Top Layer w25: C11.2@683.03,1656 683.03,1665.84 672.38,1676.5 669.18,1676.5 623,1722.68 623,2129.36 637.64,2144 1595,2144
  Bottom Layer w15: U2.44@651.03,1673.4 v1@651.03,1705
  other v1: 651.03,1705.08
NetC14_2: C14.2 R16.2 U4.11 | length 132.4
  Top Layer w15: U4.11@2904.08,1615.5 C14.2@2987,1615.5 ; C14.2@2986,1615.5 R16.2@3035.5,1615.5
NetC30_1: C30.1 R23.2 U5.8 | length 208.3
  Top Layer w12: U5.8@3265,1066.61 3265,1117.2 3298.5,1150.7 C30.1@3298.5,1172.4 3300.8,1174.7 v1(3342,1174.7)
  Bottom Layer w15: R23.2@3298.5,1167.4 3299.3,1168.2 3341.2,1168.2 v1@3342,1169
NetC37_1: C37.1 R30.2 U6.8 | length 199.3
  Top Layer w12: U6.8@3265,2129.61 3265,2179.5 3284.81,2199.31 3284.81,2200.3 3297.51,2213 C37.1@3298.5,2213 ; v1@3350,2213 v1(3351,2212)
  Top Layer w15: C37.1@3300.5,2213 v1@3350,2213
  Bottom Layer w10: R30.2@3300.5,2212 v1(3351,2212)
NetC42_1: C42.1 R2.2 U1.50 | length 168.7
  Top Layer w15: v1(1319,1706.08) 1335,1722.08 1335,1745.69 1339.31,1750 C42.1@1342.62,1750
  Top Layer w22: C42.1@1342.62,1750 1346.56,1750 1347.37,1750.81 1347.37,1754.75 1356.63,1764.01 R2.2@1356.63,1822.37
  Bottom Layer w15: U1.50@1319,1673.4 v1@1319,1706
NetC43_2: C43.2 pad.1@988,1876 R5.2 U2.50 | length 348.9
  Top Layer w12: v1@805.12,1708.79 807.11,1710.78 807.11,1714.22 813,1720.11 813,1751.76 C43.2@818.24,1757
  Top Layer w22: C43.2@818.24,1757 826.62,1757 ccw(c826.62,1780.38) 850,1780.38 R5.2@850,1827
  Top Layer w35: R5.2@850,1832 860,1822 934,1822 979.13,1867.13 989.13,1867.13 pad.1@988,1876
  Bottom Layer w15: U2.50@804.58,1673.4 v1@804.58,1706
  other v1: 805.58,1707.08
NetC45_1: C45.1 D11.1 R33.2 U7.6 | length 640.4
  Top Layer w20: D11.1@3316,281.31 3356.69,322 3461.61,322 R33.2@3470,330.39 ; v1(3470,223) 3470,322 R33.2@3470,330.39 ; R33.2@3471,331.39 R33.2@3470,330.39
  Bottom Layer w12: v1(3470,223) 3542.84,150.16 U7.6@3680.02,150.16 3702.84,150.16 3746.5,106.5 C45.1@3746.5,74
NetC46_1: C46.1 D12.1 R37.2 U10.6 | length 785.4
  Top Layer w20: D12.1@3289,1418.31 3289,1460 3344.89,1515.89 R37.2@3434.5,1515.89 3418,1499.39 v1(3418,1430)
  Bottom Layer w12: v1(3418,1430) 3418,1386 3502,1302 U10.6@3680.02,1302 3707,1302 3744.5,1264.5 C46.1@3744.5,1203
NetC47_1: C47.1 C54.2 J7.2 T3.1 T3.2 | length 395.7
  Top Layer w12: T3.2@4068.61,1231.35 T3.1@4068.61,1256.94
  Top Layer w15: T3.1@4068.61,1256.94 C47.1@4068.61,1319.74
  Top Layer w20: C54.2@4040.13,1440 C54.2@4045.5,1434.63 ; C47.1@4068.61,1319.74 C47.1@4074.5,1325.63
  Top Layer w30: C54.2@4045.5,1434.63 4045.5,1354.64 C47.1@4074.5,1325.63
  Top Layer w50: J7.2@3912,1542 4014,1440 C54.2@4040.13,1440
NetC58_1: C58.1 D1.2 T1.8
NetC58_2: C58.2 R46.2 | length 5.1
  Top Layer w20: C58.2@2546.19,777 2548,778.81 C58.2@2548,781.38
NetC59_1: C59.1 D3.2 T1.5
NetC59_2: C59.2 R47.2 | length 6.2
  Top Layer w10: C59.2@2539.62,1157 C59.2@2544,1152.62
NetC60_1: C60.1 D4.2 T2.8
NetC60_2: C60.2 R48.2 | length 15.2
  Top Layer w10: R48.2@2480,1843.62 R48.2@2484.38,1848 ; C60.2@2541.62,1848 C60.2@2548,1854.38
NetC61_1: C61.1 D6.2 T2.5
NetC61_2: C61.2 R49.2 | length 3.1
  Top Layer w20: C61.2@2546.19,2229 2548,2227.19 C61.2@2548,2226.62
NetD1_1: D1.1 D3.1 L6.1
NetD4_1: D4.1 D6.1 L7.1
NetD11_2: D11.2 R33.1 U7.5 | length 390.9
  Top Layer w20: D11.2@3316,194.69 3380.09,130.61 R33.1@3421.79,130.61 3471.61,130.61 v1(3472,131)
  Bottom Layer w12: v1(3472,131) 3472.53,130.47 U7.5@3680.02,130.47
NetD12_2: D12.2 R37.1 U10.5 | length 411.5
  Top Layer w20: D12.2@3289,1331.69 3305.59,1315.11 R37.1@3385.29,1315.11 3431.89,1315.11 v1(3433,1314)
  Bottom Layer w12: v1(3433,1314) 3464.68,1282.32 U10.5@3680.02,1282.32
NetHS_FLT_2: HS_FLT.2 R10.2 | length 113.4
  Top Layer w20: v1(3137,199) HS_FLT.2@3137,260.47
  Bottom Layer w10: R10.2@3137,251.5 R10.2@3138,252.5
  Bottom Layer w30: v1@3137,201 R10.2@3137,251.5
NetHS_OC_2: HS_OC.2 R12.2 | length 115.9
  Top Layer w10: HS_OC.2@3224,258.52 HS_OC.2@3225,257.52
  Top Layer w20: v1(3225,198) HS_OC.2@3225,257.52
  Bottom Layer w10: R12.2@3225,251.5 R12.2@3226,252.5
  Bottom Layer w30: v1(3225,198) R12.2@3225,251.5
NetJ2_2: J2.2 U8.1 | length 722.5
  Bottom Layer w15: U8.1@3522.24,254.61 3574.61,254.61 3626,306 3626,414 3652,440 4099,440 J2.2@4103,436
NetJ2_3: J2.3 U7.2 | length 365.8
  Signal Layer 2 w15: v1(3841,170) 3937,170 J2.3@4103,336
  Bottom Layer w10: v1@3840.84,169.84 v1(3841,170)
  Bottom Layer w12: U7.2@3806,169.84 v1@3840.84,169.84
NetJ3_2: J3.2 U9.5 | length 523.2
  Signal Layer 2 w15: v1(3586,1481) 3665.98,1481.02 J3.2@3914,1233
  Bottom Layer w15: v1(3586,1481) 3587.35,1481 3588.97,1479.39 U9.5@3677.76,1479.39
NetJ3_3: J3.3 U10.2 | length 280.2
  Bottom Layer w12: U10.2@3806,1321.69 3851.32,1321.69 3866,1307 3866,1146.45 3878.52,1133.93 3913.07,1133.93 J3.3@3914,1133
NetL1_2: L1.2 U1.42 | length 102.3
  Top Layer w15: L1.2@1003.63,1710 1003.63,1691.07 1007,1687.7 v1(1039.87,1687.7)
  Bottom Layer w15: v1(1039.87,1687.7) 1057.41,1670.16 1057.41,1667.87 U1.42@1070.58,1654.7
NetL2_2: L2.2 U2.42 | length 106.6
  Top Layer w15: v1(583.37,1691) L2.2@583.37,1750
  Bottom Layer w15: U2.42@556.15,1654.7 556.15,1663.78 v1(583.37,1691)
NetLDO_2: LDO.2 R21.2 | length 108.9
  Top Layer w20: v1(4071,866) LDO.2@4071,913
  Bottom Layer w10: v1(4071,866) 4071,805.5 R21.2@4072,804.5
NetLS_FLT_2: LS_FLT.2 R14.2 | length 121.8
  Top Layer w10: LS_FLT.2@3213,1335.47 LS_FLT.2@3215,1337.47
  Top Layer w20: v1(3215,1277) LS_FLT.2@3215,1337.47
  Bottom Layer w30: v1(3215,1277) R14.2@3215,1335.5
NetLS_OC_2: LS_OC.2 R17.2 | length 119.2
  Top Layer w10: LS_OC.2@3135,1332.52 LS_OC.2@3136,1333.52
  Top Layer w20: v1(3135,1278) LS_OC.2@3135,1332.52
  Bottom Layer w10: R17.2@3132,1340.01 R17.2@3135,1337.01
  Bottom Layer w30: v1(3135,1278) R17.2@3135,1337.01
NetR6_1: R6.1 U3.6 | length 2158.1
  Top Layer w10: R6.1@1238.62,1801 R6.1@1239,1801.38 ; U3.6@2706.23,546.25 U3.6@2706.48,546.5
  Top Layer w15: R6.1@1239,1801.38 v1(1239,1831) ; v1(2637,545) 2638.35,545 2639.85,546.5 U3.6@2691.48,546.5
  Signal Layer 1 w15: v1(1239,1831) 1310,1760 1598,1760 2442,916 2442,674 2551,565 2617,565 v1(2637,545)
NetR8_1: R8.1 R13.2 U5.4 | length 293.7
  Top Layer w12: U5.4@3284.68,893.39 3284.68,859.32 3300,844 3356,844 3377.61,822.39 v1(3377.61,792.39)
  Bottom Layer w15: v1(3377.61,792.39) 3389.49,804.28 3412.23,804.28 R8.1@3412.5,804.55
  Bottom Layer w20: R8.1@3412.5,804.55 R13.2@3412.5,886
NetR15_1: R15.1 U4.6 | length 2370.8
  Top Layer w15: R15.1@708.72,1807 708.72,1823.72 v1(731,1846) ; v1(2639,1616) 2639.25,1615.75 2691.23,1615.75 U4.6@2691.48,1615.5
  Signal Layer 1 w15: v1(731,1846) 731,1987 812.09,2068.09 2051.58,2068.09 2503.68,1616 v1(2639,1616)
NetR18_1: R18.1 U3.5 | length 130.8
  Top Layer w10: R18.1@2562.54,576 R18.1@2567.04,571.5
  Top Layer w15: R18.1@2567.04,571.5 U3.5@2691.48,571.5
NetR19_1: R19.1 U3.13 | length 225.7
  Top Layer w15: U3.13@2908.52,596.5 3054.5,596.5 3100,551 R19.1@3100,535.62
NetR20_1: R20.1 U3.14 | length 379.4
  Top Layer w15: U3.14@2908.52,621.5 3168.74,621.5 R20.1@3253,537.24
NetR25_2: R25.2 U5.6 | length 88.5
  Top Layer w12: U5.6@3304.37,1066.61 3304.37,1079.4 3304.46,1079.5 R25.2@3380,1079.5
NetR26_1: R26.1 R28.2 U6.4 | length 249.2
  Top Layer w12: U6.4@3284.68,1956.39 3284.78,1956.29 3284.78,1920.22 3298,1907 3334,1907 v1(3374,1947)
  Bottom Layer w10: R26.1@3410.5,1960 R26.1@3412.5,1962
  Bottom Layer w15: v1(3374,1947) 3387,1960 R26.1@3410.5,1960
  Bottom Layer w20: R26.1@3412.5,1962 R28.2@3412.5,2019
NetR29_2: R29.2 U6.7 | length 236.3
  Top Layer w12: U6.7@3284.68,2129.61 3284.68,2163.32 3301.37,2180 3438.97,2180 3446,2172.97 R29.2@3446,2141.5
NetR32_2: R32.2 U6.6 | length 82.8
  Top Layer w12: U6.6@3304.37,2129.61 3304.37,2139.91 3304.46,2140 R32.2@3376.88,2140
NetR34_1: R34.1 U8.7 | length 862.4
  Top Layer w20: v1(3067,131) R34.1@3067,175
  Signal Layer 2 w15: v1(3067,131) 3095,159 3655,159 3741,245 v1@3741,278.1
  Bottom Layer w12: v1@3736.73,280.2 3738.84,278.1 v1@3741,278.1
  Bottom Layer w15: U8.7@3677.76,280.2 v1@3736.73,280.2
  other v1: 3741,280.1
NetR35_2: R35.2 U8.2 U8.3 | length 428.4
  Bottom Layer w15: U8.2@3522.24,280.2 U8.3@3522.24,305.8 3565.8,305.8 3591.5,331.5 3591.5,566.01 R35.2@3654,628.5
NetR36_1: R36.1 U9.6 U9.7 | length 773.3
  Signal Layer 2 w15: v1(3586,1428) 3557,1399 3557,1043 v1(3587,1013)
  Bottom Layer w15: v1(3586,1428) 3586.2,1428.2 U9.7@3677.76,1428.2 U9.6@3677.76,1453.8
  Bottom Layer w20: v1(3587,1013) 3589,1013 3654,948 R36.1@3654,825.48
NetR38_1: R38.1 U9.3 | length 541.7
  Top Layer w15: R38.1@3035,1373 3036,1374 3078.62,1374 3087.62,1365 v1(3088,1365)
  Signal Layer 2 w15: v1(3088,1365) 3276,1365 3381.1,1470.1 3432.77,1470.1 3436.23,1466.64 v1(3489.26,1466.64)
  Bottom Layer w10: U9.3@3503.78,1453.8 U9.3@3522.24,1453.8
  Bottom Layer w15: v1(3489.26,1466.64) 3502.11,1453.8 U9.3@3503.78,1453.8
NetR39_1: R39.1 U4.13 | length 208.4
  Top Layer w15: U4.13@2904.08,1665.5 3048.5,1665.5 3079.69,1634.31 3079.69,1620.56 R39.1@3084,1616.24
NetR40_1: R40.1 U4.14 | length 365.7
  Top Layer w15: U4.14@2904.08,1690.5 3164.74,1690.5 R40.1@3239,1616.24
NetR41_2: R41.2 U2.49 | length 2242.1
  Top Layer w10: R41.2@2521.46,1635 R41.2@2527.46,1641
  Top Layer w15: v1(2437,1635) R41.2@2521.46,1635
  Signal Layer 1 w15: v1(778.98,1718) 778.98,1719.35 787,1727.37 787,1982 848,2043 2029,2043 v1(2437,1635)
  Bottom Layer w15: U2.49@778.98,1673.4 v1@778.98,1711
NetR42_2: R42.2 U5.7 | length 252
  Top Layer w12: U5.7@3284.68,1066.61 3284.78,1066.71 3284.78,1099.78 3309,1124 3429,1124 3446,1107 R42.2@3446,1066.5
NetR43_2: R43.2 U5.5 | length 98.5
  Top Layer w12: U5.5@3305.04,892.71 3352.22,892.71 R43.2@3388.5,929
NetR45_2: R45.2 U6.5 | length 106.1
  Top Layer w12: U6.5@3304.37,1956.39 3304.37,1949.44 3304.46,1949.34 3321.34,1949.34 3360,1988 R45.2@3387.5,1988
NetT1_1: T1.1 U5.1
NetT1_4: T1.4 U5.10
NetT2_1: T2.1 U6.1
NetT2_4: T2.4 U6.10
NetU7_1: U7.1 U10.3 U10.7 | length 1317.3
  Signal Layer 2 w15: v1(3769.65,190) 3837,257.35 v1(3837,1264)
  Bottom Layer w12: U10.7@3689.76,1321.78 3759.22,1321.78 3778.91,1302.09 U10.3@3796.25,1302.09 ; v1@3770.12,189.53 U7.1@3806,189.53 ; U10.3@3806,1302 3829.97,1302 3837,1294.97 v1(3837,1264)
NetU7_3: U7.3 U7.7 | length 134.1
  Bottom Layer w12: U7.7@3680.02,169.84 3724.16,169.84 3743.84,150.16 U7.3@3806,150.16
OC_H: U1.48 U3.3 | length 2630.5
  Top Layer w15: v1@2637.5,621.5 U3.3@2691.48,621.5
  Signal Layer 1 w15: v1(1266.39,1704.65) 1221.74,1660 1139.1,1660 1114,1685.1 1114,1813 1199,1898 1547,1898 2510,935 2510,681 2569,622 v1(2637,622)
  Bottom Layer w15: v1(1266.39,1704.65) 1266.39,1703.3 1267.82,1701.86 U1.48@1267.82,1673.4
OC_L: U2.48 U4.4 | length 2573.2
  Top Layer w15: v1(2616,1667) 2617.35,1667 2618.85,1665.5 U4.4@2691.48,1665.5
  Signal Layer 1 w15: v1(753.39,1706.08) 735.42,1706.08 701,1740.5 701,2010 787,2096 2068,2096 2497,1667 v1(2616,1667)
  Bottom Layer w15: U2.48@753.39,1673.4 v1@753.39,1706
PWM_Bot: J1.1 J3.1 U10.1 | length 686.1
  Bottom Layer w12: U10.1@3806,1341.37 3905.63,1341.37 J3.1@3914,1333
  Bottom Layer w20: J3.1@3914,1333 4415,1333 4460,1288 J1.1@4460,1278
PWM_Top: J2.1 J4.1 | length 379.4
  Top Layer w50: J2.1@4103,536 4145,578 J4.1@4465,578
SW: C1.2 C2.2 C3.1 C5.1 C10.2 C24.2 C25.2 C42.2 D2.2 ISO15VSW.1 L1.1 L4.1 pad.3@1829,1005 R2.1 R24.2 R46.1 R47.1 T1.6 T1.7 TP1.1 U1.17 U1.18 U1.19 U1.20 U1.21 U1.22 U1.23 U1.24 U1.25 U1.26 U1.27 U1.28 U1.29 U1.30 U1.31 U1.32 U1.33 U1.34 U1.35 U1.36 U1.37 U1.38 U1.39 U2.1 U2.2 U2.3 U2.4 U2.5 U2.6 U2.7 U2.8 U2.9 U2.10 U2.11 U2.12 U2.13 U2.14 U2.15 U2.16 U3.2 U3.8 | length 364.1
  Top Layer w10: C10.2@2608.62,647 2612,650.38 C10.2@2615.88,646.5
  Top Layer w15: v1(1460.04,1823.04) 1494.3,1788.79 R2.1@1558.39,1788.79 ; v1(2554,494) v1@2582,494 ; v1(2581,647) C10.2@2608.62,647 ; v1(2583,493) 2583.96,493.96 2587.49,493.96 2588.54,495 2609.65,495 2609.69,494.96 2611.96,494.96 v1@2612,495 ; v1@2612.96,494.96 2616.49,494.96 2616.54,495 2631.46,495 2631.51,495.04 2635.96,495.04 v1(2637,496) ; C10.2@2615.88,646.5 U3.2@2691.48,646.5 ; v1@2637.5,496.5 U3.8@2691.48,496.5 ; U3.8@2706.23,496.75 U3.8@2706.48,496.5
  Bottom Layer w50: v3(1165.35,953) v3@1166.35,954
  other v1: 2612,494 2321,734 2296,736 2326,756 2302,757 2311,777 2333,777 2554,907 2554,942.33 2554,977.67 2554,1013 908,1084 938,1084 968,1084 998,1084 1028,1084 1058,1084 1088,1084 1118,1084 1148,1084 1178,1084 1208,1084 953,1109 983,1109 1013,1109 1043,1109 1073,1109 1103,1109 1133,1109 1163,1109 1193,1109 1223,1109 968,1134 998,1134 1028,1134 1058,1134 1088,1134 1118,1134 1148,1134 1178,1134 1208,1134 983,1159 1013,1159 1043,1159 1073,1159 1103,1159 1133,1159 1163,1159 1193,1159 1223,1159 1671,1264 1636,1279 1671,1310.5 1636,1325.5 1671,1357 1636,1372 1671,1403.5 1636,1418.5 1671,1450 1636,1465 1671,1496.5 1636,1511.5 1671,1543 1636,1558 1164.14,1606 1192.57,1606 1221,1606 1249.43,1606 1277.86,1606 1306.29,1606 1334.71,1606 1192,1636 1221,1636 1249,1636
TEMP_H: R18.2 U1.49 | length 1900
  Top Layer w10: R18.2@2504.46,575 R18.2@2505.46,576
  Top Layer w15: v1(2448,575) R18.2@2504.46,575
  Signal Layer 1 w15: v1(1293.41,1715.39) 1293.41,1675.79 1302.2,1667 1601,1667 2364,904 2364,648 2436.04,575.96 2447.04,575.96 v1(2448,575)
  Bottom Layer w15: U1.49@1293.41,1673.4 v1(1293.41,1715.39)
TEMP_L: R41.1 U4.5 | length 99.4
  Top Layer w10: R41.1@2593.54,1637 R41.1@2597.04,1640.5
  Top Layer w15: R41.1@2597.04,1640.5 U4.5@2691.48,1640.5
Top_FET_FAULT: C40.1 C50.1 pad.1@3123,427 R10.1 R19.2 U9.1 | length 1587.3
  Top Layer w20: R19.2@3100,488.38 3100,456 pad.1@3123,427 ; v1(3140,375) 3123,392 pad.1@3123,427 ; C40.1@3150,488.38 3150,458 pad.1@3123,427
  Signal Layer 2 w15: v1(3140,375) 3179,375 3464,660 3464,1387 v1(3447,1404)
  Bottom Layer w15: v1(3447,1404) 3448.35,1404 3449.74,1402.61 U9.1@3522.24,1402.61
  Bottom Layer w30: R10.1@3140,317.5 v1(3140,375) C50.1@3140,436
Top_FET_OC: C39.1 C51.1 pad.1@3223,428 R12.1 R20.2 U9.2 | length 1583.6
  Top Layer w20: C39.1@3200,488.38 3200,451 pad.1@3223,428 ; v1(3224,375) 3223.5,375.5 3223.5,427.5 pad.1@3223,428 ; R20.2@3253,490 3253,449 3232,428 pad.1@3223,428
  Signal Layer 2 w15: v1(3224,375) 3258,375 3512,629 3512,1392 v1(3472,1432)
  Bottom Layer w15: v1(3472,1432) 3473.35,1432 3477.15,1428.2 U9.2@3522.24,1428.2
  Bottom Layer w30: v1@3225,376 C51.1@3225,434.5 ; R12.1@3226,315.5 v1@3226,373
Top_FET_PWM: pad.1@3052,426 R7.1 R34.2 Top_FET_PWM.1 | length 358.7
  Top Layer w20: R34.2@3011,175 2977,209 2977,296 3052,371 pad.1@3052,426 R7.1@3050.5,488.5
Top_FET_TEMP: U3.12
VNEG_H: C3.2 pad.1@1134,1904 U1.40 U1.41 | length 476.8
  Top Layer w10: C3.2@1001,1625 1001,1619.77 1021,1599.77 v1(1039.39,1599.77) ; C3.2@1004,1622 v1(1039.76,1622)
  Top Layer w20: v1(1115,1858) 1134,1877 pad.1@1134,1904
  Signal Layer 1 w15: v1(1039.76,1622) 1079,1661.24 1079,1822 v1(1115,1858)
  Bottom Layer w10: v1(1039.39,1599.77) 1040.38,1599.77 1046.91,1593.25 1068.05,1593.25 U1.40@1070.58,1590.73 ; v1(1039.76,1622) 1052.1,1622 1057.78,1616.32 U1.41@1070.58,1616.32
VNEG_L: C13.2 pad.1@542,1689 U2.40 U2.41 | length 147.3
  Top Layer w15: C13.2@549,1624 568,1605 v1@587,1605
  Bottom Layer w10: U2.40@541.28,1590.73 U2.40@556.15,1590.73 572.73,1590.73 v1@587,1605
  Bottom Layer w15: v1(512,1630) 525.69,1616.32 U2.41@556.15,1616.32
  other v1: 586,1604
pads on no net: J1.3 J1.4 J4.3 J4.4 R2.3 R5.3 R33.3 R37.3 SH-J1.0 SH-J2.0 SH-J3.0 T3.5 T3.7@4107,1213.63 T3.7@4107,1249.06

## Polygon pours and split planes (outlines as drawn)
GND_LV on Bottom Layer "Signal Layer 1-GND_LV" (solid, pour order 183): 2934,1296 2949,1311 2987,1311 3008,1332 3008,1488 2977,1519 2977,1744 3091,1858 3091,2239 3583,2239 3787,2239 3833,2193 3832,2192 3832,1610 3868,1575 4770,1575 4859,1486 4859,416 4466,23 3172,23 3110,85 3110,270 3005,375 3005,442 2900,442 2898,440 2898,491 2996.53,491 3008,502.47 3008,673 3140,805 3140,1121 3018,1243 2945,1243 2934,1254
15V_F on Bottom Layer "15V_F_L04_P000" (solid, pour order 0): 3079,893 3072,900 3072,1024 3080,1032 3100,1032 3100,1120 3110,1130 3806,1130 3816,1120 3816,1050 3806,1040 3183,1040 3160,1017 3160,907.4 3145.6,893 3100,893
15V_F on Bottom Layer "15V_F_L04_P004" (solid, pour order 4): 3453,1928 3456,1931 3456,1980 3495,1980 3495,1931 3498,1928 3628,1928 3687,1869 3918,1869 3918,1868 3944,1841 3944,1621 3933,1610 3893,1610 3880,1623 3880,1664 3867,1677 3749,1677 3572,1854 3256,1854 3148,1962 3086,1962 3073,1975 3073,2096.5 3081.5,2105 3148,2105 3153,2100 3153,2026 3251,1928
